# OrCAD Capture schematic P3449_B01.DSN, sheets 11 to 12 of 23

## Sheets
11 0012_3V3 DCDC and 1V8 LDO: size Custom
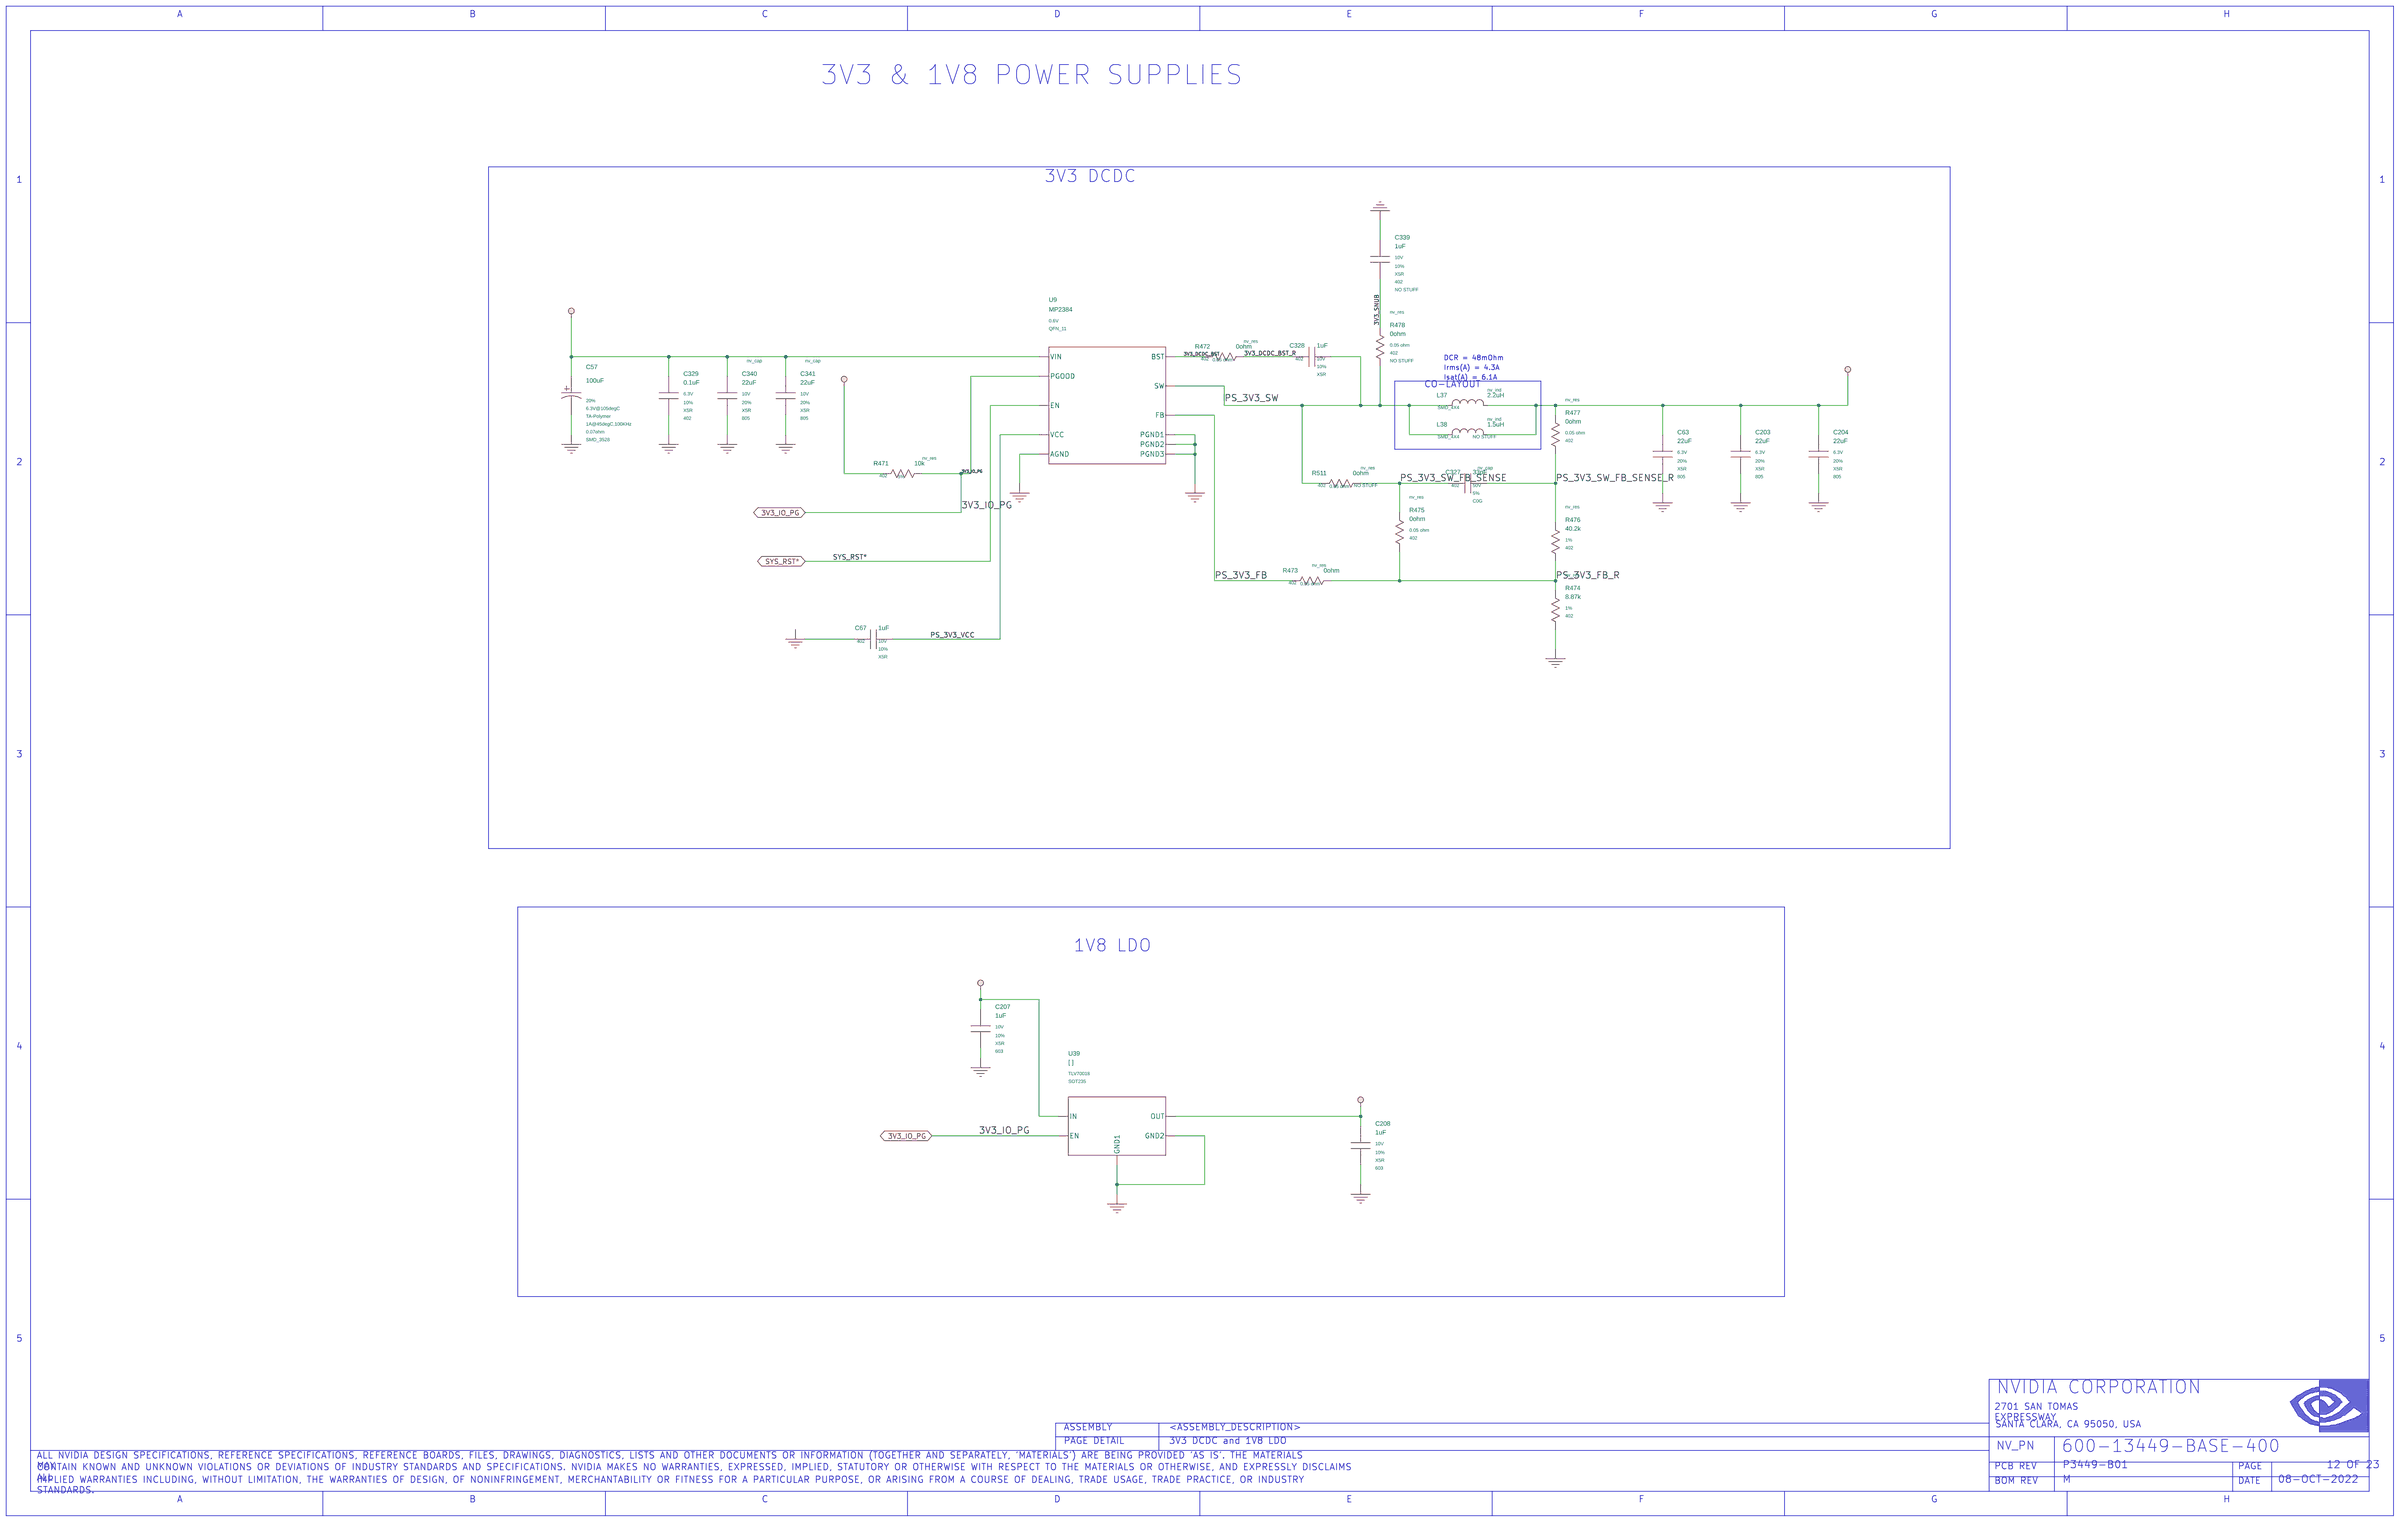
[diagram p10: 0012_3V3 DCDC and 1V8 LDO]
12 0011_DC Jack: size Custom
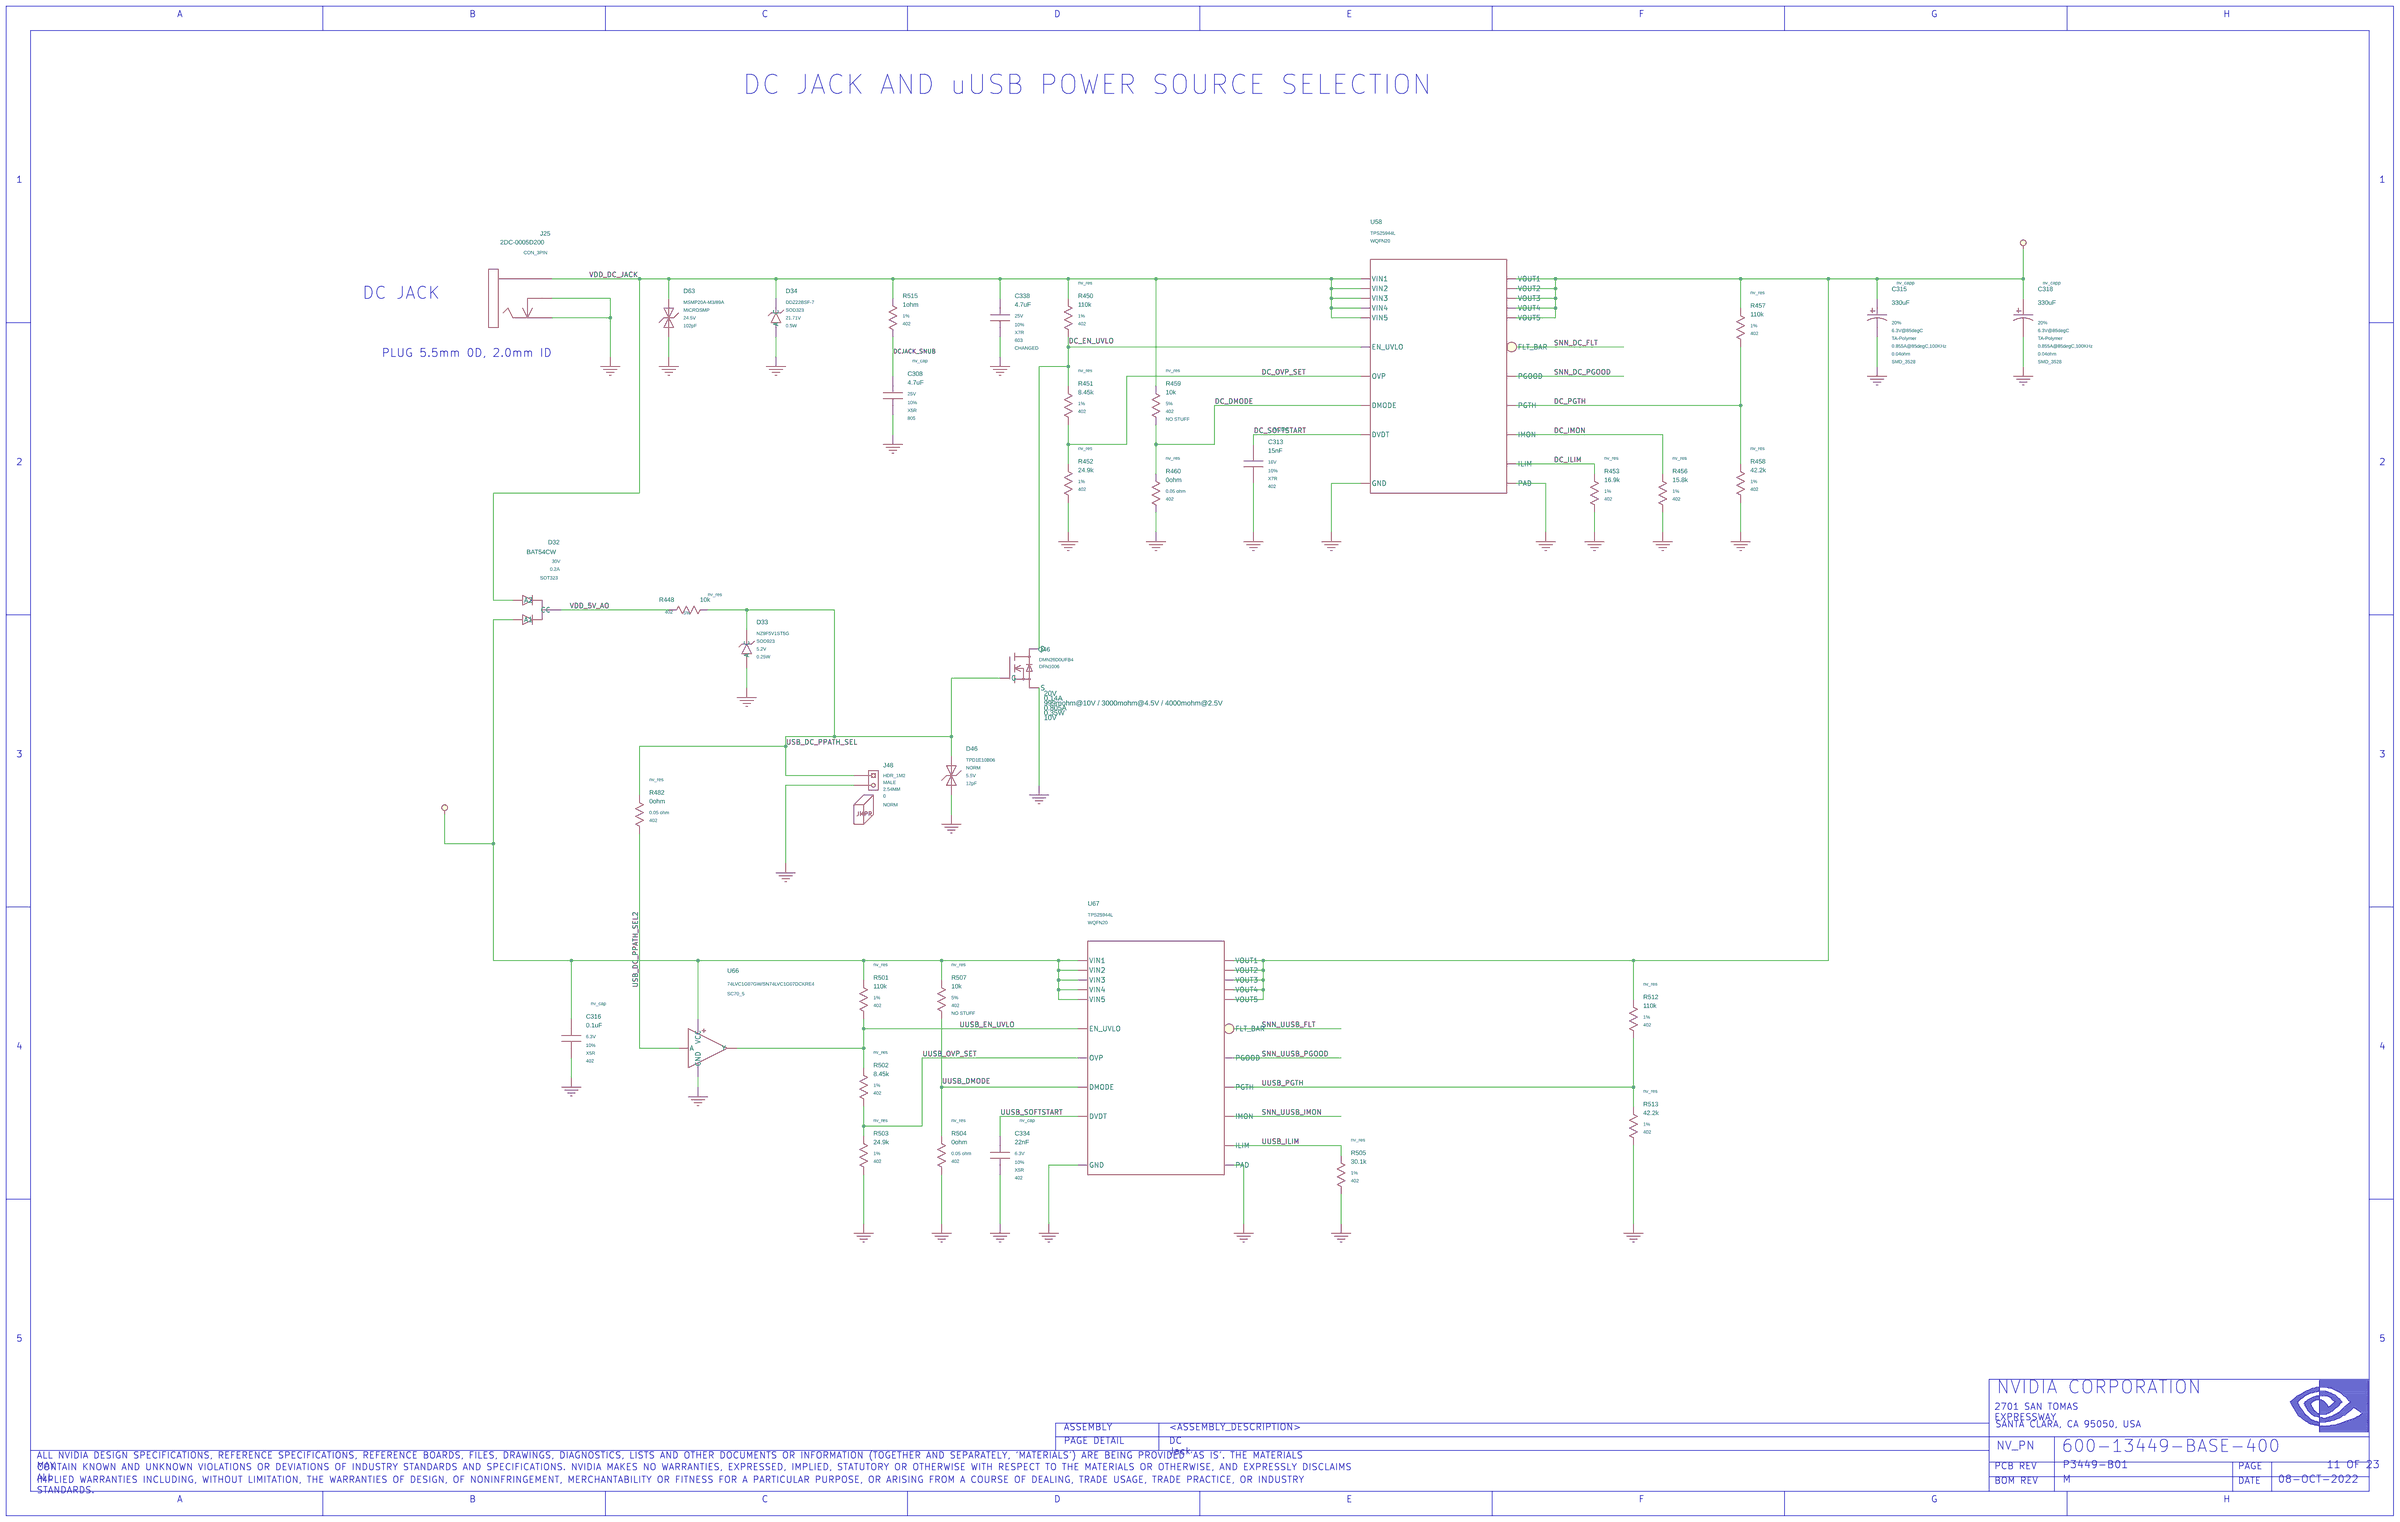
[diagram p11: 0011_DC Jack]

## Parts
sheet 0011_DC Jack
C308  4.7uF  [805]
C313  15nF  [402]
C315  330uF  [CAP_SMD_3528]
C316  0.1uF  [402]
C318  330uF  [CAP_SMD_3528]
C334  22nF  [402]
C338  4.7uF  [603]
D32  D_3PIN_CC  [SOT323]
D33  D_ZENER  [DIODE_SMD_SOD923]
D34  D_ZENER  [DIODE_SMD_SOD323_C]
D46  D_ESD  [DIODE_SMD_010X060]
D63  D_ESD  [DIODE_SMD_025X013]
J25  CON_PWR_JACK  [CON_PWR_003_TH_RA_145X090_C]
J48  HDR_1X2  [CON_HDR_001X002_TH_ST_M_P025]
Q46  Q_FET_N_ENH  [DFET_003_SMD_010X006_B]
R448  10k  [402]
R450  110k  [402]
R451  8.45k  [402]
R452  24.9k  [402]
R453  16.9k  [402]
R456  15.8k  [402]
R457  110k  [402]
R458  42.2k  [402]
R459  10k  [402]
R460  0ohm  [402]
R482  0ohm  [402]
R501  110k  [402]
R502  8.45k  [402]
R503  24.9k  [402]
R504  0ohm  [402]
R505  30.1k  [402]
R507  10k  [402]
R512  110k  [402]
R513  42.2k  [402]
R515  1ohm  [402]
U58  U_EFUSE  [QFN020R_P050_0040X0030_T026X016]
U66  U_BUF_OD  [SC70_5]
U67  U_EFUSE  [QFN020R_P050_0040X0030_T026X016]
sheet 0012_3V3 DCDC and 1V8 LDO
C57  100uF  [CAP_SMD_3528]
C63  22uF  [805]
C67  1uF  [402]
C203  22uF  [805]
C204  22uF  [805]
C207  1uF  [603]
C208  1uF  [603]
C327  33pF  [402]
C328  1uF  [402]
C329  0.1uF  [402]
C339  1uF  [402]
C340  22uF  [805]
C341  22uF  [805]
L37  2.2uH  [IND_NONRKO_SMD_040X040_H]
L38  1.5uH  [IND_NONRKO_SMD_040X040_J]
R471  10k  [402]
R472  0ohm  [402]
R473  0ohm  [402]
R474  8.87k  [402]
R475  0ohm  [402]
R476  40.2k  [402]
R477  0ohm  [402]
R478  0ohm  [402]
R511  0ohm  [402]
U9  0.6V  [QFN011Q_P050_0020]
U39  [ ]  [SOT23_5]

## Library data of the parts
C308 = C#1: ASSEMBLY: CONN_POWER; CDS_LIB: discrete; CDS_PART_NAME: C_0805-4.7UF,X5R,10%,25V,032-1141-000; CDS_PHYS_PART_NAME: C_0805-4.7UF,X5R,10%,25V,032-1141-000-032-1141-000,4.7UF; CDS_SEC: 1; CHIPS_PART_NAME: C; DEVICE_TYPENAME: C_0805-47UFX5R1025V032-1141-000-032-1141-00047UF; DRAWING: @P3449_B01_LIB.P3449_B01(SCH_1):PAGE11; IMPLEMENTATION_TYPE: X^@REFDES  %1    %2   @NV_PN; MAT: X5R; MAX_VOLTAGE: 25V; NV_PN: 032-1141-000; PATH: I350; PHYS_PAGE: 11; PSPICETEMPLATE: Pspice Model; ROT: 0; SEC: 1; SIGNAL_MODEL: nv_cap; TOL: 10%; VER: 1; XY: (-7800,5700)
C313 = C#1: ASSEMBLY: CONN_POWER; CDS_LIB: discrete; CDS_PART_NAME: C_0402-15NF,X7R,10%,16V,036-0119-000; CDS_PHYS_PART_NAME: C_0402-15NF,X7R,10%,16V,036-0119-000-036-0119-000,15NF; CDS_SEC: 1; CHIPS_PART_NAME: C; DEVICE_TYPENAME: C_0402-15NFX7R1016V036-0119-000-036-0119-00015NF; DRAWING: @P3449_B01_LIB.P3449_B01(SCH_1):PAGE11; MAT: X7R; MAX_VOLTAGE: 16V; NV_PN: 036-0119-000; PATH: I369; PHYS_PAGE: 11; ROT: 0; SEC: 1; SIGNAL_MODEL: nv_cap; TOL: 10%; VER: 1; XY: (-5950,5350)
C315 = C_POL: ASSEMBLY: CONN_POWER; CDS_LIB: discrete; CDS_PART_NAME: C_POL_SMD_3528-330UF,TA-POLYMER,20%,6.3V@85DEGC,0.04OHM,9.999UH,0.855A@85DEGC,100KHZ,032-0696-000; CDS_PHYS_PART_NAME: C_POL_SMD_3528-330UF,TA-POLYMER,20%,6.3V@85DEGC,0.04OHM,9.999UH,0.855A@85DEGC,100KHZ,032-0696-000-032-0696-000,330UF; CDS_SEC: 1; DEVICE_TYPENAME: C_POL_SMD_3528-330UFTA-POLYMER2063V85DEGC004OHM9999UH0855A85DEGC100KHZ032-0696-000-032-0696-000330UF; DRAWING: @P3449_B01_LIB.P3449_B01(SCH_1):PAGE11; ESL: 9.999uH; ESR: 0.04ohm; MAT: TA-Polymer; MAX_VOLTAGE: 6.3V@85degC; NV_PN: 032-0696-000; PACK_TYPE: SMD_3528; PATH: I385; PHYS_PAGE: 11; RIPPLE_CURRENT: 0.855A@85degC,100KHz; ROT: 0; SEC: 1; SIGNAL_MODEL: nv_capp; TOL: 20%; VER: 1; XY: (-2750,6100)
C316 = C#1: ASSEMBLY: CONN_POWER; CDS_LIB: discrete; CDS_PART_NAME: C_0402-0.1UF,X5R,10%,6.3V,039-0007-000; CDS_PHYS_PART_NAME: C_0402-0.1UF,X5R,10%,6.3V,039-0007-000-0.1UF,039-0007-000; CDS_SEC: 1; CHIPS_PART_NAME: C; DEVICE_TYPENAME: C_0402-01UFX5R1063V039-0007-000-01UF039-0007-000; DRAWING: @P3449_B01_LIB.P3449_B01(SCH_1):PAGE11; MAT: X5R; MAX_VOLTAGE: 6.3V; NV_PN: 039-0007-000; PATH: I398; PHYS_PAGE: 11; ROT: 0; SEC: 1; SIGNAL_MODEL: nv_cap; TOL: 10%; VER: 1; XY: (-9450,2400)
C318 = C_POL: ASSEMBLY: CONN_POWER; CDS_LIB: discrete; CDS_PART_NAME: C_POL_SMD_3528-330UF,TA-POLYMER,20%,6.3V@85DEGC,0.04OHM,9.999UH,0.855A@85DEGC,100KHZ,032-0696-000; CDS_PHYS_PART_NAME: C_POL_SMD_3528-330UF,TA-POLYMER,20%,6.3V@85DEGC,0.04OHM,9.999UH,0.855A@85DEGC,100KHZ,032-0696-000-032-0696-000,330UF; CDS_SEC: 1; DEVICE_TYPENAME: C_POL_SMD_3528-330UFTA-POLYMER2063V85DEGC004OHM9999UH0855A85DEGC100KHZ032-0696-000-032-0696-000330UF; DRAWING: @P3449_B01_LIB.P3449_B01(SCH_1):PAGE11; ESL: 9.999uH; ESR: 0.04ohm; MAT: TA-Polymer; MAX_VOLTAGE: 6.3V@85degC; NV_PN: 032-0696-000; PACK_TYPE: SMD_3528; PATH: I400; PHYS_PAGE: 11; RIPPLE_CURRENT: 0.855A@85degC,100KHz; ROT: 0; SEC: 1; SIGNAL_MODEL: nv_capp; TOL: 20%; VER: 1; XY: (-2000,6100)
C334 = C#1: ASSEMBLY: CONN_POWER; CDS_LIB: discrete; CDS_PART_NAME: C_0402-15NF,X7R,10%,16V,036-0119-000; CDS_PHYS_PART_NAME: C_0402-15NF,X7R,10%,16V,036-0119-000-036-0119-000,15NF; CDS_SEC: 1; CHIPS_PART_NAME: C; DEVICE_TYPENAME: C_0402-15NFX7R1016V036-0119-000-036-0119-00015NF; DRAWING: @P3449_B01_LIB.P3449_B01(SCH_1):PAGE11; MAT: X5R; MAX_VOLTAGE: 6.3V; NV_PN: 036-0119-000; PATH: I438; PHYS_PAGE: 11; ROT: 0; SEC: 1; SIGNAL_MODEL: nv_cap; TOL: 10%; VER: 1; XY: (-7250,1800)
C338 = C#1: ASSEMBLY: CONN_POWER; CDS_LIB: discrete; CDS_PART_NAME: C_0603-1UF,X5R,20%,25V,032-0882-000; CDS_PHYS_PART_NAME: C_0603-1UF,X5R,20%,25V,032-0882-000-032-0882-000,1UF; CDS_SEC: 1; CHIPS_PART_NAME: C; DEVICE_TYPENAME: C_0603-1UFX5R2025V032-0882-000-032-0882-0001UF; DRAWING: @P3449_B01_LIB.P3449_B01(SCH_1):PAGE11; MAT: X7R; MAX_VOLTAGE: 25V; NV_PN: 032-0882-000; PATH: I452; PHYS_PAGE: 11; ROT: 0; SEC: 1; SIGNAL_MODEL: nv_capp; SKU: CHANGED; TOL: 10%; VER: 1; XY: (-7250,6100)
D32 = D_3PIN_CC: ASSEMBLY: CONN_POWER; CDS_LIB: discrete; CDS_PART_NAME: D_3PIN_CC_SOT323-BAT54CW,1 PAIR - COMMON CATHODE,30V,0.6A,1V@0.1A,0.2A,091-0022-000; CDS_PHYS_PART_NAME: D_3PIN_CC_SOT323-BAT54CW,1 PAIR - COMMON CATHODE,30V,0.6A,1V@0.1A,0.2A,091-0022-000-091-0022-000; CDS_SEC: 1; CONFIGURATION: 1 Pair - Common Cathode; CONTINUOUS_CURRENT: 0.2A; DEVICE_TYPENAME: D_3PIN_CC_SOT323-BAT54CW1PAIR-COMMONCATHODE30V06A1V01A02A091-0022-000-091-0022-000; DRAWING: @P3449_B01_LIB.P3449_B01(SCH_1):PAGE11; FORWARD_VOLTAGE: 1V@0.1A; MAX_CURRENT: 0.6A; MAX_VOLTAGE: 30V; NV_NAME: BAT54CW; NV_PN: 091-0022-000; PATH: I373; PHYS_PAGE: 11; ROT: 2; SEC: 1; VER: 1; XY: (-9600,4600)
D33 = D_ZENER: ASSEMBLY: CONN_POWER; CDS_LIB: discrete; CDS_PART_NAME: D_ZENER_SOD923-NZ9F5V1ST5G,5.2V,5MA,0.9V@10MA,0.25W,090-0309-000; CDS_PHYS_PART_NAME: D_ZENER_SOD923-NZ9F5V1ST5G,5.2V,5MA,0.9V@10MA,0.25W,090-0309-000-090-0309-000; CDS_SEC: 1; CONTINUOUS_CURRENT: 0.25W; DEVICE_TYPENAME: D_ZENER_SOD923-NZ9F5V1ST5G52V5MA09V10MA025W090-0309-000-090-0309-000; DRAWING: @P3449_B01_LIB.P3449_B01(SCH_1):PAGE11; FORWARD_VOLTAGE: 0.9V@10mA; MAX_CURRENT: 5mA; MAX_VOLTAGE: 5.2V; NV_NAME: NZ9F5V1ST5G; NV_PN: 090-0309-000; PACK_TYPE: SOD923; PATH: I374; PHYS_PAGE: 11; ROT: 0; SEC: 1; VER: 2; XY: (-8550,4400)
D34 = D_ZENER: ASSEMBLY: CONN_POWER; CDS_LIB: discrete; CDS_PART_NAME: D_ZENER_SOD323-DDZ22BSF-7,21.71V,5MA,0.9V@10MA,0.5W,090-0377-000; CDS_PHYS_PART_NAME: D_ZENER_SOD323-DDZ22BSF-7,21.71V,5MA,0.9V@10MA,0.5W,090-0377-000-090-0377-000; CDS_SEC: 1; CONTINUOUS_CURRENT: 0.5W; DEVICE_TYPENAME: D_ZENER_SOD323-DDZ22BSF-72171V5MA09V10MA05W090-0377-000-090-0377-000; DRAWING: @P3449_B01_LIB.P3449_B01(SCH_1):PAGE11; FORWARD_VOLTAGE: 0.9V@10mA; MAX_CURRENT: 5mA; MAX_VOLTAGE: 21.71V; NV_NAME: DDZ22BSF-7; NV_PN: 090-0377-000; PACK_TYPE: SOD323; PATH: I404; PHYS_PAGE: 11; ROT: 0; SEC: 1; VER: 2; XY: (-8400,6100)
D46 = D_ESD: ASSEMBLY: CONN_POWER; BREAKDOWN_VOLTAGE_MIN_TYP: 6V; CAPACITANCE_MAX_TYP: 12pF; CDS_LIB: discrete; CDS_PART_NAME: D_ESD_NORM-TPD1E10B06,1 LINE,BI-DIRECTIONAL,5.5V,0.1UA,6V,10V@1A,12PF,090-0243-000; CDS_PHYS_PART_NAME: D_ESD_NORM-TPD1E10B06,1 LINE,BI-DIRECTIONAL,5.5V,0.1UA,6V,10V@1A,12PF,090-0243-000-090-0243-000; CDS_SEC: 1; CLAMPING_VOLTAGE: 10V@1A; CONFIGURATION: 1 Line; DEVICE_TYPENAME: D_ESD_NORM-TPD1E10B061LINEBI-DIRECTIONAL55V01UA6V10V1A12PF090-0243-000-090-0243-000; DRAWING: @P3449_B01_LIB.P3449_B01(SCH_1):PAGE11; MAX_REVERSE_LEAKAGE_CURRENT: 0.1uA; MAX_REVERSE_VOLTAGE: 5.5V; NV_NAME: TPD1E10B06; NV_PN: 090-0243-000; PACK_TYPE: NORM; PATH: I406; PHYS_PAGE: 11; POLARITY: Bi-Directional; ROT: 0; SEC: 1; VER: 2; XY: (-7500,3750)
D63 = D_ESD: ASSEMBLY: CONN_POWER; BREAKDOWN_VOLTAGE_MIN_TYP: 22.2V; CAPACITANCE_MAX_TYP: 102pF; CDS_LIB: discrete; CDS_PART_NAME: D_ESD_MICROSMP-MSMP20A-M3/89A,1 LINE,UNI-DIRECTIONAL,24.5V,1UA,22.2V,42.8V@23.4A,102PF,090-0378-000; CDS_PHYS_PART_NAME: D_ESD_MICROSMP-MSMP20A-M3/89A,1 LINE,UNI-DIRECTIONAL,24.5V,1UA,22.2V,42.8V@23.4A,102PF,090-0378-000-090-0378-000; CDS_SEC: 1; CLAMPING_VOLTAGE: 42.8V@23.4A; CONFIGURATION: 1 Line; DEVICE_TYPENAME: D_ESD_MICROSMP-MSMP20A-M389A1LINEUNI-DIRECTIONAL245V1UA222V428V234A102PF090-0378-000-090-0378-000; DRAWING: @P3449_B01_LIB.P3449_B01(SCH_1):PAGE11; MAX_REVERSE_LEAKAGE_CURRENT: 1uA; MAX_REVERSE_VOLTAGE: 24.5V; NV_NAME: MSMP20A-M3/89A; NV_PN: 090-0378-000; PACK_TYPE: MICROSMP; PATH: I432; PHYS_PAGE: 11; POLARITY: Uni-Directional; ROT: 0; SEC: 1; VER: 2; XY: (-8950,6100)
J25 = CON_PWR_JACK: ANGLE: 90; ASSEMBLY: CONN_POWER; CDS_LIB: electro_mechanic; CDS_PART_NAME: CON_PWR_JACK_CON_3PIN-2DC-0005D200,FEMALE,N/A,90,YES,NO,NO,NO,NO,24V,5A,064-0377-000; CDS_PHYS_PART_NAME: CON_PWR_JACK_CON_3PIN-2DC-0005D200,FEMALE,N/A,90,YES,NO,NO,NO,NO,24V,5A,064-0377-000-064-0377-000; CDS_SEC: 1; DEVICE_TYPENAME: CON_PWR_JACK_CON_3PIN-2DC-0005D200FEMALENA90YESNONONONO24V5A064-0377-000-064-0377-000; DRAWING: @P3449_B01_LIB.P3449_B01(SCH_1):PAGE11; EMI_GROUND_TAB: NO; GENDER: FEMALE; LATCHING: NO; MAX_CURRENT: 5A; MAX_VOLTAGE: 24V; NV_NAME: 2DC-0005D200; NV_PN: 064-0377-000; PACK_TYPE: CON_3PIN; PATH: I220; PHYS_PAGE: 11; PITCH: N/A; REFLOW: YES; ROT: 2; SEC: 1; SHIELDED: NO; SHROUDED: NO; VER: 1; XY: (-9850,6300)
J48 = HDR_1X2: ANGLE: 0; ASSEMBLY: CONN_POWER; CDS_LIB: electro_mechanic; CDS_PART_NAME: HDR_1X2_NORM-HDR_1M2,MALE,2.54MM,0,NO,NO,NO,250V,3A,074-0117-000; CDS_PHYS_PART_NAME: HDR_1X2_NORM-HDR_1M2,MALE,2.54MM,0,NO,NO,NO,250V,3A,074-0117-000-074-0117-000; CDS_SEC: 1; DEVICE_TYPENAME: HDR_1X2_NORM-HDR_1M2MALE254MM0NONONO250V3A074-0117-000-074-0117-000; DRAWING: @P3449_B01_LIB.P3449_B01(SCH_1):PAGE11; GENDER: MALE; LATCHING: NO; MAX_CURRENT: 3A; MAX_VOLTAGE: 250V; NV_NAME: HDR_1M2; NV_PN: 074-0117-000; PACK_TYPE: NORM; PATH: I361; PHYS_PAGE: 11; PITCH: 2.54MM; REFLOW: NO; ROT: 0; SEC: 1; SEC_TYPE: NORM; SHROUDED: NO; VER: 3; XY: (-7900,3750)
Q46 = Q_FET_N_ENH#1: ASSEMBLY: CONN_POWER; CDS_LIB: discrete; CDS_PART_NAME: Q_FET_N_ENH_DFN1006-DMN26D0UFB4,20V,999MOHM@10V / 3000MOHM@4.5V / 4000MOHM@2.5V,0.14A,0.805A,10V,0.35W,999NC@10V / 0NC@4.5V / A; CDS_PHYS_PART_NAME: Q_FET_N_ENH_DFN1006-DMN26D0UFB4,20V,999MOHM@10V / 3000MOHM@4.5V / 4000MOHM@2.5V,0.14A,0.805A,10V,0.35W,999NC@10V / 0NC@4.5V / B; CDS_SEC: 1; CONTINUOUS_CURRENT: 0.14A; CaptureCellPackProp: Q_FET_N_ENH##1; DEVICE_TYPENAME: Q_FET_N_ENH_DFN1006-DMN26D0UFB420V999MOHM10V3000MOHM45V4000MOHM25V014A0805A10V035W999NC10V0NC45VB; DRAWING: @P3449_B01_LIB.P3449_B01(SCH_1):PAGE11; MAX_CURRENT: 0.805A; MAX_VOLTAGE: 20V; MAX_WATTAGE: 0.35W; NV_NAME: DMN26D0UFB4; NV_PN: 300-0868-000; PACK_TYPE: DFN1006; PATH: I377; PHYS_PAGE: 11; Q_G: 999nC@10V / 0nC@4.5V / 999nC@2.5V; ROT: 0; R_DS_ON: 999mohm@10V / 3000mohm@4.5V / 4000mohm@2.5V; SEC: 1; VER: 2; V_BE_GS: 10V; XY: (-7150,4300)
R448 = R#1: ASSEMBLY: CONN_POWER; CDS_LIB: discrete; CDS_PART_NAME: R_0402-10K,5 %,62.5MW,195-0486-000; CDS_PHYS_PART_NAME: R_0402-10K,5 %,62.5MW,195-0486-000-10K,195-0486-000; CDS_SEC: 1; CHIPS_PART_NAME: R; DEVICE_TYPENAME: R_0402-10K5625MW195-0486-000-10K195-0486-000; DRAWING: @P3449_B01_LIB.P3449_B01(SCH_1):PAGE11; MAX_WATTAGE: 62.5mW; NV_PN: 195-0486-000; PATH: I380; PHYS_PAGE: 11; ROT: 0; SEC: 1; SIGNAL_MODEL: nv_res; TOL: 5%; VER: 1; XY: (-8850,4600)
R450 = R: ASSEMBLY: CONN_POWER; CDS_LIB: discrete; CDS_PART_NAME: R_0402-110K,1 %,62.5MW,195-0026-000; CDS_PHYS_PART_NAME: R_0402-110K,1 %,62.5MW,195-0026-000-110K,195-0026-000; CDS_SEC: 1; DEVICE_TYPENAME: R_0402-110K1625MW195-0026-000-110K195-0026-000; DRAWING: @P3449_B01_LIB.P3449_B01(SCH_1):PAGE11; MAX_WATTAGE: 62.5mW; NV_PN: 195-0026-000; PATH: I367; PHYS_PAGE: 11; ROT: 0; SEC: 1; SIGNAL_MODEL: nv_res; TOL: 1%; VER: 2; XY: (-6900,6100)
R451 = R: ASSEMBLY: CONN_POWER; CDS_LIB: discrete; CDS_PART_NAME: R_0402-8.45K,1 %,62.5MW,195-0449-000; CDS_PHYS_PART_NAME: R_0402-8.45K,1 %,62.5MW,195-0449-000-195-0449-000,8.45K; CDS_SEC: 1; DEVICE_TYPENAME: R_0402-845K1625MW195-0449-000-195-0449-000845K; DRAWING: @P3449_B01_LIB.P3449_B01(SCH_1):PAGE11; MAX_WATTAGE: 62.5mW; NV_PN: 195-0449-000; PATH: I383; PHYS_PAGE: 11; ROT: 0; SEC: 1; SIGNAL_MODEL: nv_res; TOL: 1%; VER: 2; XY: (-6900,5650)
R452 = R: ASSEMBLY: CONN_POWER; CDS_LIB: discrete; CDS_PART_NAME: R_0402-24.9K,1 %,62.5MW,195-0195-000; CDS_PHYS_PART_NAME: R_0402-24.9K,1 %,62.5MW,195-0195-000-195-0195-000,24.9K; CDS_SEC: 1; DEVICE_TYPENAME: R_0402-249K1625MW195-0195-000-195-0195-000249K; DRAWING: @P3449_B01_LIB.P3449_B01(SCH_1):PAGE11; MAX_WATTAGE: 62.5mW; NV_PN: 195-0195-000; PATH: I384; PHYS_PAGE: 11; ROT: 0; SEC: 1; SIGNAL_MODEL: nv_res; TOL: 1%; VER: 2; XY: (-6900,5250)
R453 = R: ASSEMBLY: CONN_POWER; CDS_LIB: discrete; CDS_PART_NAME: R_0402-16.9K,1 %,62.5MW,195-0115-000; CDS_PHYS_PART_NAME: R_0402-16.9K,1 %,62.5MW,195-0115-000-16.9K,195-0115-000; CDS_SEC: 1; DEVICE_TYPENAME: R_0402-169K1625MW195-0115-000-169K195-0115-000; DRAWING: @P3449_B01_LIB.P3449_B01(SCH_1):PAGE11; MAX_WATTAGE: 62.5mW; NV_PN: 195-0115-000; PATH: I371; PHYS_PAGE: 11; ROT: 0; SEC: 1; SIGNAL_MODEL: nv_res; TOL: 1%; VER: 2; XY: (-4200,5200)
R456 = R: ASSEMBLY: CONN_POWER; CDS_LIB: discrete; CDS_PART_NAME: R_0402-15.8K,1 %,62.5MW,195-0100-000; CDS_PHYS_PART_NAME: R_0402-15.8K,1 %,62.5MW,195-0100-000-15.8K,195-0100-000; CDS_SEC: 1; DEVICE_TYPENAME: R_0402-158K1625MW195-0100-000-158K195-0100-000; DRAWING: @P3449_B01_LIB.P3449_B01(SCH_1):PAGE11; MAX_WATTAGE: 62.5mW; NV_PN: 195-0100-000; PATH: I390; PHYS_PAGE: 11; ROT: 0; SEC: 1; SIGNAL_MODEL: nv_res; TOL: 1%; VER: 2; XY: (-3850,5200)
R457 = R: ASSEMBLY: CONN_POWER; CDS_LIB: discrete; CDS_PART_NAME: R_0402-110K,1 %,62.5MW,195-0026-000; CDS_PHYS_PART_NAME: R_0402-110K,1 %,62.5MW,195-0026-000-110K,195-0026-000; CDS_SEC: 1; DEVICE_TYPENAME: R_0402-110K1625MW195-0026-000-110K195-0026-000; DRAWING: @P3449_B01_LIB.P3449_B01(SCH_1):PAGE11; MAX_WATTAGE: 62.5mW; NV_PN: 195-0026-000; PATH: I392; PHYS_PAGE: 11; ROT: 0; SEC: 1; SIGNAL_MODEL: nv_res; TOL: 1%; VER: 2; XY: (-3450,6050)
R458 = R: ASSEMBLY: CONN_POWER; CDS_LIB: discrete; CDS_PART_NAME: R_0402-42.2K,1 %,62.5MW,195-0305-000; CDS_PHYS_PART_NAME: R_0402-42.2K,1 %,62.5MW,195-0305-000-195-0305-000,42.2K; CDS_SEC: 1; DEVICE_TYPENAME: R_0402-422K1625MW195-0305-000-195-0305-000422K; DRAWING: @P3449_B01_LIB.P3449_B01(SCH_1):PAGE11; MAX_WATTAGE: 62.5mW; NV_PN: 195-0305-000; PATH: I391; PHYS_PAGE: 11; ROT: 0; SEC: 1; SIGNAL_MODEL: nv_res; TOL: 1%; VER: 2; XY: (-3450,5250)
R459 = R: ASSEMBLY: CONN_POWER; CDS_LIB: discrete; CDS_PART_NAME: R_0402-10K,5 %,62.5MW,195-0486-000; CDS_PHYS_PART_NAME: R_0402-10K,5 %,62.5MW,195-0486-000-10K,195-0486-000; CDS_SEC: 1; DEVICE_TYPENAME: R_0402-10K5625MW195-0486-000-10K195-0486-000; DRAWING: @P3449_B01_LIB.P3449_B01(SCH_1):PAGE11; MAX_WATTAGE: 62.5mW; NV_PN: 195-0486-000; PATH: I395; PHYS_PAGE: 11; ROT: 0; SEC: 1; SIGNAL_MODEL: nv_res; SKU: NO STUFF; TOL: 5%; VER: 2; XY: (-6450,5650)
R460 = R: ASSEMBLY: CONN_POWER; CDS_LIB: discrete; CDS_PART_NAME: R_0402-0OHM,0.05 OHM,62.5MW,195-2655-000; CDS_PHYS_PART_NAME: R_0402-0OHM,0.05 OHM,62.5MW,195-2655-000-0OHM,195-2655-000; CDS_SEC: 1; DEVICE_TYPENAME: R_0402-0OHM005OHM625MW195-2655-000-0OHM195-2655-000; DRAWING: @P3449_B01_LIB.P3449_B01(SCH_1):PAGE11; MAX_WATTAGE: 62.5mW; NV_PN: 195-2655-000; PATH: I396; PHYS_PAGE: 11; ROT: 0; SEC: 1; SIGNAL_MODEL: nv_res; TOL: 0.05 ohm; VER: 2; XY: (-6450,5200)
R482 = R: ASSEMBLY: CONN_POWER; CDS_LIB: discrete; CDS_PART_NAME: R_0402-0OHM,0.05 OHM,62.5MW,195-2655-000; CDS_PHYS_PART_NAME: R_0402-0OHM,0.05 OHM,62.5MW,195-2655-000-0OHM,195-2655-000; CDS_SEC: 1; DEVICE_TYPENAME: R_0402-0OHM005OHM625MW195-2655-000-0OHM195-2655-000; DRAWING: @P3449_B01_LIB.P3449_B01(SCH_1):PAGE11; MAX_WATTAGE: 62.5mW; NV_PN: 195-2655-000; PATH: I416; PHYS_PAGE: 11; ROT: 0; SEC: 1; SIGNAL_MODEL: nv_res; TOL: 0.05 ohm; VER: 2; XY: (-9100,3550)
R501 = R: ASSEMBLY: CONN_POWER; CDS_LIB: discrete; CDS_PART_NAME: R_0402-110K,1 %,62.5MW,195-0026-000; CDS_PHYS_PART_NAME: R_0402-110K,1 %,62.5MW,195-0026-000-110K,195-0026-000; CDS_SEC: 1; DEVICE_TYPENAME: R_0402-110K1625MW195-0026-000-110K195-0026-000; DRAWING: @P3449_B01_LIB.P3449_B01(SCH_1):PAGE11; MAX_WATTAGE: 62.5mW; NV_PN: 195-0026-000; PATH: I443; PHYS_PAGE: 11; ROT: 0; SEC: 1; SIGNAL_MODEL: nv_res; TOL: 1%; VER: 2; XY: (-7950,2600)
R502 = R: ASSEMBLY: CONN_POWER; CDS_LIB: discrete; CDS_PART_NAME: R_0402-8.45K,1 %,62.5MW,195-0449-000; CDS_PHYS_PART_NAME: R_0402-8.45K,1 %,62.5MW,195-0449-000-195-0449-000,8.45K; CDS_SEC: 1; DEVICE_TYPENAME: R_0402-845K1625MW195-0449-000-195-0449-000845K; DRAWING: @P3449_B01_LIB.P3449_B01(SCH_1):PAGE11; MAX_WATTAGE: 62.5mW; NV_PN: 195-0449-000; PATH: I444; PHYS_PAGE: 11; ROT: 0; SEC: 1; SIGNAL_MODEL: nv_res; TOL: 1%; VER: 2; XY: (-7950,2150)
R503 = R: ASSEMBLY: CONN_POWER; CDS_LIB: discrete; CDS_PART_NAME: R_0402-24.9K,1 %,62.5MW,195-0195-000; CDS_PHYS_PART_NAME: R_0402-24.9K,1 %,62.5MW,195-0195-000-195-0195-000,24.9K; CDS_SEC: 1; DEVICE_TYPENAME: R_0402-249K1625MW195-0195-000-195-0195-000249K; DRAWING: @P3449_B01_LIB.P3449_B01(SCH_1):PAGE11; MAX_WATTAGE: 62.5mW; NV_PN: 195-0195-000; PATH: I445; PHYS_PAGE: 11; ROT: 0; SEC: 1; SIGNAL_MODEL: nv_res; TOL: 1%; VER: 2; XY: (-7950,1800)
R504 = R: ASSEMBLY: CONN_POWER; CDS_LIB: discrete; CDS_PART_NAME: R_0402-0OHM,0.05 OHM,62.5MW,195-2655-000; CDS_PHYS_PART_NAME: R_0402-0OHM,0.05 OHM,62.5MW,195-2655-000-0OHM,195-2655-000; CDS_SEC: 1; DEVICE_TYPENAME: R_0402-0OHM005OHM625MW195-2655-000-0OHM195-2655-000; DRAWING: @P3449_B01_LIB.P3449_B01(SCH_1):PAGE11; MAX_WATTAGE: 62.5mW; NV_PN: 195-2655-000; PATH: I441; PHYS_PAGE: 11; ROT: 0; SEC: 1; SIGNAL_MODEL: nv_res; TOL: 0.05 ohm; VER: 2; XY: (-7550,1800)
R505 = R: ASSEMBLY: CONN_POWER; CDS_LIB: discrete; CDS_PART_NAME: R_0402-30.1K,1 %,62.5MW,195-0270-000; CDS_PHYS_PART_NAME: R_0402-30.1K,1 %,62.5MW,195-0270-000-195-0270-000,35.7K; CDS_SEC: 1; DEVICE_TYPENAME: R_0402-357K1625MW195-0270-000-195-0270-000357K; DRAWING: @P3449_B01_LIB.P3449_B01(SCH_1):PAGE11; MAX_WATTAGE: 62.5mW; NV_PN: 195-0270-000; PATH: I434; PHYS_PAGE: 11; ROT: 0; SEC: 1; SIGNAL_MODEL: nv_res; TOL: 1%; VER: 2; XY: (-5500,1700)
R507 = R: ASSEMBLY: CONN_POWER; CDS_LIB: discrete; CDS_PART_NAME: R_0402-10K,5 %,62.5MW,195-0486-000; CDS_PHYS_PART_NAME: R_0402-10K,5 %,62.5MW,195-0486-000-10K,195-0486-000; CDS_SEC: 1; DEVICE_TYPENAME: R_0402-10K5625MW195-0486-000-10K195-0486-000; DRAWING: @P3449_B01_LIB.P3449_B01(SCH_1):PAGE11; MAX_WATTAGE: 62.5mW; NV_PN: 195-0486-000; PATH: I451; PHYS_PAGE: 11; ROT: 0; SEC: 1; SIGNAL_MODEL: nv_res; SKU: NO STUFF; TOL: 5%; VER: 2; XY: (-7550,2600)
R512 = R: ASSEMBLY: CONN_POWER; CDS_LIB: discrete; CDS_PART_NAME: R_0402-110K,1 %,62.5MW,195-0026-000; CDS_PHYS_PART_NAME: R_0402-110K,1 %,62.5MW,195-0026-000-110K,195-0026-000; CDS_SEC: 1; DEVICE_TYPENAME: R_0402-110K1625MW195-0026-000-110K195-0026-000; DRAWING: @P3449_B01_LIB.P3449_B01(SCH_1):PAGE11; MAX_WATTAGE: 62.5mW; NV_PN: 195-0026-000; PATH: I454; PHYS_PAGE: 11; ROT: 0; SEC: 1; SIGNAL_MODEL: nv_res; TOL: 1%; VER: 2; XY: (-4000,2500)
R513 = R: ASSEMBLY: CONN_POWER; CDS_LIB: discrete; CDS_PART_NAME: R_0402-42.2K,1 %,62.5MW,195-0305-000; CDS_PHYS_PART_NAME: R_0402-42.2K,1 %,62.5MW,195-0305-000-195-0305-000,42.2K; CDS_SEC: 1; DEVICE_TYPENAME: R_0402-422K1625MW195-0305-000-195-0305-000422K; DRAWING: @P3449_B01_LIB.P3449_B01(SCH_1):PAGE11; MAX_WATTAGE: 62.5mW; NV_PN: 195-0305-000; PATH: I455; PHYS_PAGE: 11; ROT: 0; SEC: 1; SIGNAL_MODEL: nv_res; TOL: 1%; VER: 2; XY: (-4000,1950)
R515 = R: ASSEMBLY: CONN_POWER; CDS_LIB: discrete; CDS_PART_NAME: R_0402-5.6OHM,5 %,62.5MW,195-0609-000; CDS_PHYS_PART_NAME: R_0402-5.6OHM,5 %,62.5MW,195-0609-000-195-0609-000,5.6OHM; CDS_SEC: 1; DEVICE_TYPENAME: R_0402-56OHM5625MW195-0609-000-195-0609-00056OHM; DRAWING: @P3449_B01_LIB.P3449_B01(SCH_1):PAGE11; MAX_WATTAGE: 62.5mW; NV_PN: 195-0609-000; PATH: I457; PHYS_PAGE: 11; ROT: 0; SEC: 1; TOL: 1%; VER: 2; XY: (-7800,6100)
U58 = U_EFUSE#1: ASSEMBLY: CONN_POWER; CDS_LIB: power_supply; CDS_PART_NAME: U_EFUSE_WQFN20-TPS25944L,-0.3V..18V,2.7V..20V,5.2A,OTHER,315-1109-000; CDS_PHYS_PART_NAME: U_EFUSE_WQFN20-TPS25944L,-0.3V..18V,2.7V..20V,5.2A,OTHER,315-1109-000-315-1109-000; CDS_SEC: 1; DEVICE_TYPENAME: U_EFUSE_WQFN20-TPS25944L-03V18V27V20V52AOTHER315-1109-000-315-1109-000; DRAWING: @P3449_B01_LIB.P3449_B01(SCH_1):PAGE11; MAX_CURRENT: 5.2A; MAX_VOLTAGE: 2.7V..20V; NV_NAME: TPS25944L; NV_PN: 315-1109-000; OUTPUT_VOLTAGE: -0.3V..18V; PACK_TYPE: WQFN20; PATH: I386; PHYS_PAGE: 11; ROT: 0; SEC: 1; TYPE: Other; VER: 3; XY: (-5000,5800)
U66 = U_BUF_OD: ASSEMBLY: CONN_POWER; CDS_LIB: logic; CDS_PART_NAME: U_BUF_OD_SC70_5-74LVC1G07GW/SN74LVC1G07DCKRE4,BUFFER - OPEN DRAIN,115-0138-000; CDS_PHYS_PART_NAME: U_BUF_OD_SC70_5-74LVC1G07GW/SN74LVC1G07DCKRE4,BUFFER - OPEN DRAIN,115-0138-000-115-0138-000; CDS_SEC: 1; DEVICE_TYPENAME: U_BUF_OD_SC70_5-74LVC1G07GWSN74LVC1G07DCKRE4BUFFER-OPENDRAIN115-0138-000-115-0138-000; DRAWING: @P3449_B01_LIB.P3449_B01(SCH_1):PAGE11; FUNCTION: Buffer - Open Drain; NV_NAME: 74LVC1G07GW/SN74LVC1G07DCKRE4; NV_PN: 115-0138-000; PATH: I450; PHYS_PAGE: 11; ROT: 0; SEC: 1; VER: 1; XY: (-8750,2350)
U67 = U_EFUSE#1: ASSEMBLY: CONN_POWER; CDS_LIB: power_supply; CDS_PART_NAME: U_EFUSE_WQFN20-TPS25944L,-0.3V..18V,2.7V..20V,5.2A,OTHER,315-1109-000; CDS_PHYS_PART_NAME: U_EFUSE_WQFN20-TPS25944L,-0.3V..18V,2.7V..20V,5.2A,OTHER,315-1109-000-315-1109-000; CDS_SEC: 1; DEVICE_TYPENAME: U_EFUSE_WQFN20-TPS25944L-03V18V27V20V52AOTHER315-1109-000-315-1109-000; DRAWING: @P3449_B01_LIB.P3449_B01(SCH_1):PAGE11; MAX_CURRENT: 5.2A; MAX_VOLTAGE: 2.7V..20V; NV_NAME: TPS25944L; NV_PN: 315-1109-000; OUTPUT_VOLTAGE: -0.3V..18V; PACK_TYPE: WQFN20; PATH: I433; PHYS_PAGE: 11; ROT: 0; SEC: 1; TYPE: Other; VER: 3; XY: (-6450,2300)
C57 = C_POL: ASSEMBLY: 3V3_DCDC; CDS_LIB: discrete; CDS_PART_NAME: C_POL_SMD_3528-100UF,TA-POLYMER,20%,6.3V@105DEGC,0.07OHM,9.999UH,1A@45DEGC,100KHZ,041-0092-000; CDS_PHYS_PART_NAME: C_POL_SMD_3528-100UF,TA-POLYMER,20%,6.3V@105DEGC,0.07OHM,9.999UH,1A@45DEGC,100KHZ,041-0092-000-041-0092-000,100UF; CDS_SEC: 1; DEVICE_TYPENAME: C_POL_SMD_3528-100UFTA-POLYMER2063V105DEGC007OHM9999UH1A45DEGC100KHZ041-0092-000-041-0092-000100UF; DRAWING: @P3449_B01_LIB.P3449_B01(SCH_1):PAGE12; ESL: 9.999uH; ESR: 0.07ohm; MAT: TA-Polymer; MAX_VOLTAGE: 6.3V@105degC; NV_PN: 041-0092-000; PACK_TYPE: SMD_3528; PATH: I27; PHYS_PAGE: 12; RIPPLE_CURRENT: 1A@45degC,100KHz; ROT: 0; SEC: 1; SIGNAL_MODEL: nv_capp; TOL: 20%; VER: 1; XY: (-9250,5600)
C63 = C#1: ASSEMBLY: 3V3_DCDC; CDS_LIB: discrete; CDS_PART_NAME: C_0805-22UF,X5R,20%,6.3V,039-0127-000; CDS_PHYS_PART_NAME: C_0805-22UF,X5R,20%,6.3V,039-0127-000-039-0127-000,22UF; CDS_SEC: 1; CHIPS_PART_NAME: C; DEVICE_TYPENAME: C_0805-22UFX5R2063V039-0127-000-039-0127-00022UF; DRAWING: @P3449_B01_LIB.P3449_B01(SCH_1):PAGE12; MAT: X5R; MAX_VOLTAGE: 6.3V; NV_PN: 039-0127-000; PATH: I19; PHYS_PAGE: 12; ROT: 0; SEC: 1; SIGNAL_MODEL: nv_capp; TOL: 20%; VER: 1; XY: (-3650,5300)
C67 = C: ASSEMBLY: 3V3_DCDC; CDS_LIB: discrete; CDS_PART_NAME: C_0402-1UF,X5R,10%,10V,039-0140-000; CDS_PHYS_PART_NAME: C_0402-1UF,X5R,10%,10V,039-0140-000-039-0140-000,1UF; CDS_SEC: 1; DEVICE_TYPENAME: C_0402-1UFX5R1010V039-0140-000-039-0140-0001UF; DRAWING: @P3449_B01_LIB.P3449_B01(SCH_1):PAGE12; MAT: X5R; MAX_VOLTAGE: 10V; NV_PN: 039-0140-000; PATH: I77; PHYS_PAGE: 12; ROT: 0; SEC: 1; SIGNAL_MODEL: nv_cap; TOL: 10%; VER: 2; XY: (-7700,4350)
C203 = C#1: ASSEMBLY: 3V3_DCDC; CDS_LIB: discrete; CDS_PART_NAME: C_0805-22UF,X5R,20%,6.3V,039-0127-000; CDS_PHYS_PART_NAME: C_0805-22UF,X5R,20%,6.3V,039-0127-000-039-0127-000,22UF; CDS_SEC: 1; CHIPS_PART_NAME: C; DEVICE_TYPENAME: C_0805-22UFX5R2063V039-0127-000-039-0127-00022UF; DRAWING: @P3449_B01_LIB.P3449_B01(SCH_1):PAGE12; MAT: X5R; MAX_VOLTAGE: 6.3V; NV_PN: 039-0127-000; PATH: I17; PHYS_PAGE: 12; ROT: 0; SEC: 1; SIGNAL_MODEL: nv_capp; TOL: 20%; VER: 1; XY: (-3250,5300)
C204 = C#1: ASSEMBLY: 3V3_DCDC; CDS_LIB: discrete; CDS_PART_NAME: C_0805-22UF,X5R,20%,6.3V,039-0127-000; CDS_PHYS_PART_NAME: C_0805-22UF,X5R,20%,6.3V,039-0127-000-039-0127-000,22UF; CDS_SEC: 1; CHIPS_PART_NAME: C; DEVICE_TYPENAME: C_0805-22UFX5R2063V039-0127-000-039-0127-00022UF; DRAWING: @P3449_B01_LIB.P3449_B01(SCH_1):PAGE12; MAT: X5R; MAX_VOLTAGE: 6.3V; NV_PN: 039-0127-000; PATH: I15; PHYS_PAGE: 12; ROT: 0; SEC: 1; SIGNAL_MODEL: nv_capp; TOL: 20%; VER: 1; XY: (-2850,5300)
C207 = C#1: ASSEMBLY: 1V8_LDO; CDS_LIB: discrete; CDS_PART_NAME: C_0603-1UF,X5R,10%,10V,039-0038-000; CDS_PHYS_PART_NAME: C_0603-1UF,X5R,10%,10V,039-0038-000-039-0038-000,1UF; CDS_SEC: 1; CHIPS_PART_NAME: C; DEVICE_TYPENAME: C_0603-1UFX5R1010V039-0038-000-039-0038-0001UF; DRAWING: @P3449_B01_LIB.P3449_B01(SCH_1):PAGE12; MAT: X5R; MAX_VOLTAGE: 10V; NV_PN: 039-0038-000; PATH: I47; PHYS_PAGE: 12; ROT: 0; SEC: 1; SIGNAL_MODEL: nv_cap; TOL: 10%; VER: 1; XY: (-7150,2350)
C208 = C#1: ASSEMBLY: 1V8_LDO; CDS_LIB: discrete; CDS_PART_NAME: C_0603-1UF,X5R,10%,10V,039-0038-000; CDS_PHYS_PART_NAME: C_0603-1UF,X5R,10%,10V,039-0038-000-039-0038-000,1UF; CDS_SEC: 1; CHIPS_PART_NAME: C; DEVICE_TYPENAME: C_0603-1UFX5R1010V039-0038-000-039-0038-0001UF; DRAWING: @P3449_B01_LIB.P3449_B01(SCH_1):PAGE12; MAT: X5R; MAX_VOLTAGE: 10V; NV_PN: 039-0038-000; PATH: I44; PHYS_PAGE: 12; ROT: 0; SEC: 1; SIGNAL_MODEL: nv_cap; TOL: 10%; VER: 1; XY: (-5200,1750)
C327 = C: ASSEMBLY: 3V3_DCDC; CDS_LIB: discrete; CDS_PART_NAME: C_0402-33PF,C0G,5%,50V,035-0028-000; CDS_PHYS_PART_NAME: C_0402-33PF,C0G,5%,50V,035-0028-000-035-0028-000,33PF; CDS_SEC: 1; DEVICE_TYPENAME: C_0402-33PFC0G550V035-0028-000-035-0028-00033PF; DRAWING: @P3449_B01_LIB.P3449_B01(SCH_1):PAGE12; MAT: C0G; MAX_VOLTAGE: 50V; NV_PN: 035-0028-000; PATH: I58; PHYS_PAGE: 12; ROT: 0; SEC: 1; SIGNAL_MODEL: nv_cap; TOL: 5%; VER: 2; XY: (-4650,5150)
C328 = C: ASSEMBLY: 3V3_DCDC; CDS_LIB: discrete; CDS_PART_NAME: C_0402-1UF,X5R,10%,10V,039-0140-000; CDS_PHYS_PART_NAME: C_0402-1UF,X5R,10%,10V,039-0140-000-039-0140-000,1UF; CDS_SEC: 1; DEVICE_TYPENAME: C_0402-1UFX5R1010V039-0140-000-039-0140-0001UF; DRAWING: @P3449_B01_LIB.P3449_B01(SCH_1):PAGE12; MAT: X5R; MAX_VOLTAGE: 10V; NV_PN: 039-0140-000; PATH: I54; PHYS_PAGE: 12; ROT: 0; SEC: 1; SIGNAL_MODEL: nv_cap; TOL: 10%; VER: 2; XY: (-5450,5800)
C329 = C#1: ASSEMBLY: 3V3_DCDC; CDS_LIB: discrete; CDS_PART_NAME: C_0402-0.1UF,X5R,10%,6.3V,039-0007-000; CDS_PHYS_PART_NAME: C_0402-0.1UF,X5R,10%,6.3V,039-0007-000-0.1UF,039-0007-000; CDS_SEC: 1; CHIPS_PART_NAME: C; DEVICE_TYPENAME: C_0402-01UFX5R1063V039-0007-000-01UF039-0007-000; DRAWING: @P3449_B01_LIB.P3449_B01(SCH_1):PAGE12; MAT: X5R; MAX_VOLTAGE: 6.3V; NV_PN: 039-0007-000; PATH: I69; PHYS_PAGE: 12; ROT: 0; SEC: 1; SIGNAL_MODEL: nv_cap; TOL: 10%; VER: 1; XY: (-8750,5600)
C339 = C#1: ASSEMBLY: 3V3_DCDC; CDS_LIB: discrete; CDS_PART_NAME: C_0402-1UF,X5R,10%,10V,039-0140-000; CDS_PHYS_PART_NAME: C_0402-1UF,X5R,10%,10V,039-0140-000-039-0140-000,1UF; CDS_SEC: 1; CHIPS_PART_NAME: C; DEVICE_TYPENAME: C_0402-1UFX5R1010V039-0140-000-039-0140-0001UF; DRAWING: @P3449_B01_LIB.P3449_B01(SCH_1):PAGE12; MAT: X5R; MAX_VOLTAGE: 10V; NV_PN: 039-0140-000; PATH: I80; PHYS_PAGE: 12; ROT: 0; SEC: 1; SIGNAL_MODEL: nv_capp; SKU: NO STUFF; TOL: 10%; VER: 1; XY: (-5100,6300)
C340 = C#1: ASSEMBLY: 3V3_DCDC; CDS_LIB: discrete; CDS_PART_NAME: C_0805-22UF,X5R,20%,10V,032-1108-000; CDS_PHYS_PART_NAME: C_0805-22UF,X5R,20%,10V,032-1108-000-032-1108-000,22UF; CDS_SEC: 1; CHIPS_PART_NAME: C; DEVICE_TYPENAME: C_0805-22UFX5R2010V032-1108-000-032-1108-00022UF; DRAWING: @P3449_B01_LIB.P3449_B01(SCH_1):PAGE12; MAT: X5R; MAX_VOLTAGE: 10V; NV_PN: 032-1108-000; PATH: I88; PHYS_PAGE: 12; ROT: 0; SEC: 1; SIGNAL_MODEL: nv_cap; TOL: 20%; VER: 1; XY: (-8450,5600)
C341 = C#1: ASSEMBLY: 3V3_DCDC; CDS_LIB: discrete; CDS_PART_NAME: C_0805-22UF,X5R,20%,10V,032-1108-000; CDS_PHYS_PART_NAME: C_0805-22UF,X5R,20%,10V,032-1108-000-032-1108-000,22UF; CDS_SEC: 1; CHIPS_PART_NAME: C; DEVICE_TYPENAME: C_0805-22UFX5R2010V032-1108-000-032-1108-00022UF; DRAWING: @P3449_B01_LIB.P3449_B01(SCH_1):PAGE12; MAT: X5R; MAX_VOLTAGE: 10V; NV_PN: 032-1108-000; PATH: I87; PHYS_PAGE: 12; ROT: 0; SEC: 1; SIGNAL_MODEL: nv_cap; TOL: 20%; VER: 1; XY: (-8150,5600)
L37 = L: ASSEMBLY: 3V3_DCDC; CDS_LIB: discrete; CDS_PART_NAME: L_SMD_4X4-2.2UH,IRON CORE,20%,4.3A,6.1A,0.048OHM,0@0HZ,0HZ,130-0938-000; CDS_PHYS_PART_NAME: L_SMD_4X4-2.2UH,IRON CORE,20%,4.3A,6.1A,0.048OHM,0@0HZ,0HZ,130-0938-000-130-0938-000,2.2UH; CDS_SEC: 1; CONTINUOUS_CURRENT: 4.3A; DC_RESISTANCE: 0.048ohm; DEVICE_TYPENAME: L_SMD_4X4-22UHIRONCORE2043A61A0048OHM00HZ0HZ130-0938-000-130-0938-00022UH; DRAWING: @P3449_B01_LIB.P3449_B01(SCH_1):PAGE12; MAT: IRON CORE; MAX_CURRENT: 6.1A; NV_PN: 130-0938-000; PACK_TYPE: SMD_4X4; PATH: I53; PHYS_PAGE: 12; PLACEMENT_NOTE: CO-LAYOUT WITH L38; Q: 0@0Hz; ROT: 0; SEC: 1; SELF_RESONANCE_FREQ: 0Hz; SIGNAL_MODEL: nv_ind; TOL: 20%; VER: 1; XY: (-4650,5550)
L38 = L: ASSEMBLY: 3V3_DCDC; CDS_LIB: discrete; CDS_PART_NAME: L_SMD_4X4-1.5UH,METAL POWDER,20%,7.4A,8.8A,0.0166OHM,0@0HZ,0HZ,130-0990-000; CDS_PHYS_PART_NAME: L_SMD_4X4-1.5UH,METAL POWDER,20%,7.4A,8.8A,0.0166OHM,0@0HZ,0HZ,130-0990-000-1.5UH,130-0990-000; CDS_SEC: 1; CONTINUOUS_CURRENT: 7.4A; DC_RESISTANCE: 0.0166ohm; DEVICE_TYPENAME: L_SMD_4X4-15UHMETALPOWDER2074A88A00166OHM00HZ0HZ130-0990-000-15UH130-0990-000; DRAWING: @P3449_B01_LIB.P3449_B01(SCH_1):PAGE12; MAT: metal powder; MAX_CURRENT: 8.8A; NV_PN: 130-0990-000; PACK_TYPE: SMD_4X4; PATH: I91; PHYS_PAGE: 12; PLACEMENT_NOTE: CO-LAYOUT WITH L37; Q: 0@0Hz; ROT: 0; SEC: 1; SELF_RESONANCE_FREQ: 0Hz; SIGNAL_MODEL: nv_ind; SKU: NO STUFF; TOL: 20%; VER: 1; XY: (-4650,5400)
R471 = R#1: ASSEMBLY: 3V3_DCDC; CDS_LIB: discrete; CDS_PART_NAME: R_0402-10K,5 %,62.5MW,195-0486-000; CDS_PHYS_PART_NAME: R_0402-10K,5 %,62.5MW,195-0486-000-10K,195-0486-000; CDS_SEC: 1; CHIPS_PART_NAME: R; DEVICE_TYPENAME: R_0402-10K5625MW195-0486-000-10K195-0486-000; DRAWING: @P3449_B01_LIB.P3449_B01(SCH_1):PAGE12; MAX_WATTAGE: 62.5mW; NV_PN: 195-0486-000; PATH: I67; PHYS_PAGE: 12; ROT: 0; SEC: 1; SIGNAL_MODEL: nv_res; TOL: 5%; VER: 1; XY: (-7550,5200)
R472 = R#1: ASSEMBLY: 3V3_DCDC; CDS_LIB: discrete; CDS_PART_NAME: R_0402-0OHM,0.05 OHM,62.5MW,195-2655-000; CDS_PHYS_PART_NAME: R_0402-0OHM,0.05 OHM,62.5MW,195-2655-000-0OHM,195-2655-000; CDS_SEC: 1; CHIPS_PART_NAME: R; DEVICE_TYPENAME: R_0402-0OHM005OHM625MW195-2655-000-0OHM195-2655-000; DRAWING: @P3449_B01_LIB.P3449_B01(SCH_1):PAGE12; MAX_WATTAGE: 62.5mW; NV_PN: 195-2655-000; PATH: I61; PHYS_PAGE: 12; ROT: 0; SEC: 1; SIGNAL_MODEL: nv_res; TOL: 0.05 ohm; VER: 1; XY: (-5900,5800)
R473 = R#1: ASSEMBLY: 3V3_DCDC; CDS_LIB: discrete; CDS_PART_NAME: R_0402-0OHM,0.05 OHM,62.5MW,195-2655-000; CDS_PHYS_PART_NAME: R_0402-0OHM,0.05 OHM,62.5MW,195-2655-000-0OHM,195-2655-000; CDS_SEC: 1; CHIPS_PART_NAME: R; DEVICE_TYPENAME: R_0402-0OHM005OHM625MW195-2655-000-0OHM195-2655-000; DRAWING: @P3449_B01_LIB.P3449_B01(SCH_1):PAGE12; MAX_WATTAGE: 62.5mW; NV_PN: 195-2655-000; PATH: I83; PHYS_PAGE: 12; ROT: 0; SEC: 1; SIGNAL_MODEL: nv_res; TOL: 0.05 ohm; VER: 1; XY: (-5450,4650)
R474 = R: ASSEMBLY: 3V3_DCDC; CDS_LIB: discrete; CDS_PART_NAME: R_0402-8.87K,1 %,62.5MW,195-0459-000; CDS_PHYS_PART_NAME: R_0402-8.87K,1 %,62.5MW,195-0459-000-195-0459-000,8.87K; CDS_SEC: 1; DEVICE_TYPENAME: R_0402-887K1625MW195-0459-000-195-0459-000887K; DRAWING: @P3449_B01_LIB.P3449_B01(SCH_1):PAGE12; MAX_WATTAGE: 62.5mW; NV_PN: 195-0459-000; PATH: I56; PHYS_PAGE: 12; ROT: 0; SEC: 1; SIGNAL_MODEL: nv_res; TOL: 1%; VER: 2; XY: (-4200,4500)
R475 = R: ASSEMBLY: 3V3_DCDC; CDS_LIB: discrete; CDS_PART_NAME: R_0402-0OHM,0.05 OHM,62.5MW,195-2655-000; CDS_PHYS_PART_NAME: R_0402-0OHM,0.05 OHM,62.5MW,195-2655-000-0OHM,195-2655-000; CDS_SEC: 1; DEVICE_TYPENAME: R_0402-0OHM005OHM625MW195-2655-000-0OHM195-2655-000; DRAWING: @P3449_B01_LIB.P3449_B01(SCH_1):PAGE12; MAX_WATTAGE: 62.5mW; NV_PN: 195-2655-000; PATH: I85; PHYS_PAGE: 12; ROT: 0; SEC: 1; SIGNAL_MODEL: nv_res; TOL: 0.05 ohm; VER: 2; XY: (-5000,4900)
R476 = R: ASSEMBLY: 3V3_DCDC; CDS_LIB: discrete; CDS_PART_NAME: R_0402-40.2K,1 %,62.5MW,195-0295-000; CDS_PHYS_PART_NAME: R_0402-40.2K,1 %,62.5MW,195-0295-000-195-0295-000,40.2K; CDS_SEC: 1; DEVICE_TYPENAME: R_0402-402K1625MW195-0295-000-195-0295-000402K; DRAWING: @P3449_B01_LIB.P3449_B01(SCH_1):PAGE12; MAX_WATTAGE: 62.5mW; NV_PN: 195-0295-000; PATH: I86; PHYS_PAGE: 12; ROT: 0; SEC: 1; SIGNAL_MODEL: nv_res; TOL: 1%; VER: 2; XY: (-4200,4850)
R477 = R: ASSEMBLY: 3V3_DCDC; CDS_LIB: discrete; CDS_PART_NAME: R_0402-0OHM,0.05 OHM,62.5MW,195-2655-000; CDS_PHYS_PART_NAME: R_0402-0OHM,0.05 OHM,62.5MW,195-2655-000-0OHM,195-2655-000; CDS_SEC: 1; DEVICE_TYPENAME: R_0402-0OHM005OHM625MW195-2655-000-0OHM195-2655-000; DRAWING: @P3449_B01_LIB.P3449_B01(SCH_1):PAGE12; MAX_WATTAGE: 62.5mW; NV_PN: 195-2655-000; PATH: I71; PHYS_PAGE: 12; ROT: 0; SEC: 1; SIGNAL_MODEL: nv_res; TOL: 0.05 ohm; VER: 2; XY: (-4200,5400)
R478 = R: ASSEMBLY: 3V3_DCDC; CDS_LIB: discrete; CDS_PART_NAME: R_0402-0OHM,0.05 OHM,62.5MW,195-2655-000; CDS_PHYS_PART_NAME: R_0402-0OHM,0.05 OHM,62.5MW,195-2655-000-0OHM,195-2655-000; CDS_SEC: 1; DEVICE_TYPENAME: R_0402-0OHM005OHM625MW195-2655-000-0OHM195-2655-000; DRAWING: @P3449_B01_LIB.P3449_B01(SCH_1):PAGE12; MAX_WATTAGE: 62.5mW; NV_PN: 195-2655-000; PATH: I79; PHYS_PAGE: 12; ROT: 0; SEC: 1; SIGNAL_MODEL: nv_res; SKU: NO STUFF; TOL: 0.05 ohm; VER: 2; XY: (-5100,5850)
R511 = R#1: ASSEMBLY: 3V3_DCDC; CDS_LIB: discrete; CDS_PART_NAME: R_0402-0OHM,0.05 OHM,62.5MW,195-2655-000; CDS_PHYS_PART_NAME: R_0402-0OHM,0.05 OHM,62.5MW,195-2655-000-0OHM,195-2655-000; CDS_SEC: 1; CHIPS_PART_NAME: R; DEVICE_TYPENAME: R_0402-0OHM005OHM625MW195-2655-000-0OHM195-2655-000; DRAWING: @P3449_B01_LIB.P3449_B01(SCH_1):PAGE12; MAX_WATTAGE: 62.5mW; NV_PN: 195-2655-000; PATH: I84; PHYS_PAGE: 12; ROT: 0; SEC: 1; SIGNAL_MODEL: nv_res; SKU: NO STUFF; TOL: 0.05 ohm; VER: 1; XY: (-5300,5150)
U9 = U_BUCK_FET_1PH: ASSEMBLY: 3V3_DCDC; CDS_LIB: power_supply; CDS_PART_NAME: U_BUCK_FET_1PH_QFN_11-MP2384,BUCK,1PH,700KHZ,NONE,0.6V..13V,5%,0.6V,26V,4A,3.6W,316-0613-000; CDS_PHYS_PART_NAME: U_BUCK_FET_1PH_QFN_11-MP2384,BUCK,1PH,700KHZ,NONE,0.6V..13V,5%,0.6V,26V,4A,3.6W,316-0613-000-0.6V,316-0613-000; CDS_SEC: 1; DEVICE_TYPENAME: U_BUCK_FET_1PH_QFN_11-MP2384BUCK1PH700KHZNONE06V13V506V26V4A36W316-0613-000-06V316-0613-000; DRAWING: @P3449_B01_LIB.P3449_B01(SCH_1):PAGE12; MAX_CURRENT: 4A; MAX_VOLTAGE: 26V; MAX_WATTAGE: 3.6W; MODE: Buck; NV_NAME: MP2384; NV_PN: 316-0613-000; OUTPUT_VOLTAGE: 0.6V..13V; PACK_TYPE: QFN_11; PATH: I78; PHASES: 1Ph; PHYS_PAGE: 12; PROGRAMMABLE: None; ROT: 0; SEC: 1; SWITCHING_FREQ: 700KHz; TOL: 5%; VER: 16; XY: (-6500,5550)
U39 = U_VREG_5PIN: ASSEMBLY: 1V8_LDO; CDS_LIB: power_supply; CDS_PART_NAME: U_VREG_5PIN_SOT235-TLV70018,LOW DROP OUT/FIXED,0.25V@0.2A,1.8V..1.8V,2%,[ ],5.5V,0.2A,0.5W,315-0620-000; CDS_PHYS_PART_NAME: U_VREG_5PIN_SOT235-TLV70018,LOW DROP OUT/FIXED,0.25V@0.2A,1.8V..1.8V,2%,[ ],5.5V,0.2A,0.5W,315-0620-000-315-0620-000,[ ]; CDS_SEC: 1; DEVICE_TYPENAME: U_VREG_5PIN_SOT235-TLV70018LOWDROPOUTFIXED025V02A18V18V255V02A05W315-0620-000-315-0620-000; DRAWING: @P3449_B01_LIB.P3449_B01(SCH_1):PAGE12; FORWARD_VOLTAGE: 0.25V@0.2A; MAX_CURRENT: 0.2A; MAX_VOLTAGE: 5.5V; MAX_WATTAGE: 0.5W; NV_NAME: TLV70018; NV_PN: 315-0620-000; OUTPUT_VOLTAGE: 1.8V..1.8V; PACK_TYPE: SOT235; PATH: I42; PHYS_PAGE: 12; ROT: 0; SEC: 1; TOL: 2%; TYPE: Low Drop Out/Fixed; VER: 15; XY: (-6450,1850)

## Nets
3V3_DCDC_BST: R472.1 U9.7(BST)
3V3_DCDC_BST_R: C328.1 R472.2
3V3_IO_PG: R471.2 U9.5(PGOOD) U39.3(EN) ; also on sheet 6 15
3V3_SNUB: C339.2 R478.1
GND: C57.2 C63.2 C67.1 C203.2 C204.2 C207.2 C208.2 C308.2 C313.2 C315.2 C316.2 C318.2 C329.2 C334.2 C338.2 C339.1 C340.2 C341.2 D33.2(A) D34.2(A) D46.2 D63.2 J25.2 J25.3 J48.2 Q46.2(S) R452.2 R453.2 R456.2 R458.2 R460.2 R474.2 R503.2 R504.2 R505.2 R513.2 U9.2(PGND1) U9.3(PGND2) U9.4(PGND3) U9.9(AGND) U39.2(GND1) U39.4(GND2) U58.16(GND) U58.21(PAD) U66.3(GND) U67.16(GND) U67.21(PAD) ; also on sheet 1 3 4 5 6 7 8 9 10 13 14 15 16 19
VDD_1V8: C208.1 U39.5(OUT) ; also on sheet 3 4 6 7 9 19
VDD_3V3_SYS: C63.1 C203.1 C204.1 C207.1 L37.2 L38.2 R471.1 R477.1 U39.1(IN) ; also on sheet 3 4 5 6 7 8 9 18 19
VDD_5V_AO: D32.3(CC) R448.1
VDD_5V_IN: C57.1 C315.1 C318.1 C329.1 C340.1 C341.1 R457.1 R512.1 U9.1(VIN) U58.4(VOUT1) U58.5(VOUT2) U58.6(VOUT3) U58.7(VOUT4) U58.8(VOUT5) U67.4(VOUT1) U67.5(VOUT2) U67.6(VOUT3) U67.7(VOUT4) U67.8(VOUT5) ; also on sheet 3 4 7 10 14 15 19
VDD_5V_USB: C316.1 D32.1(A1) R501.1 R507.1 U66.5(VCC) U67.9(VIN1) U67.10(VIN2) U67.11(VIN3) U67.12(VIN4) U67.13(VIN5) ; also on sheet 16
VDD_DC_JACK: C338.1 D32.2(A2) D34.1(C) D63.1 J25.1 R450.1 R459.1 R515.1 U58.9(VIN1) U58.10(VIN2) U58.11(VIN3) U58.12(VIN4) U58.13(VIN5)
DC_DMODE: R459.2 R460.1 U58.1(DMODE)
DC_EN_UVLO: Q46.3(D) R450.2 R451.1 U58.14(EN_UVLO)
DC_ILIM: R453.1 U58.17(ILIM)
DC_IMON: R456.1 U58.19(IMON)
DC_OVP_SET: R451.2 R452.1 U58.15(OVP)
DC_PGTH: R457.2 R458.1 U58.3(PGTH)
DC_SOFTSTART: C313.1 U58.18(DVDT)
DCJACK_SNUB: C308.1 R515.2
PS_3V3_FB: R473.1 U9.10(FB)
PS_3V3_FB_R: R473.2 R474.1 R475.2 R476.2
PS_3V3_SW: C328.2 L37.1 L38.1 R478.2 R511.1 U9.6(SW)
PS_3V3_SW_FB_SENSE: C327.1 R475.1 R511.2
PS_3V3_SW_FB_SENSE_R: C327.2 R476.1 R477.2
PS_3V3_VCC: C67.2 U9.8(VCC)
SNN_DC_FLT: U58.20(FLT_BAR)
SNN_DC_PGOOD: U58.2(PGOOD)
SNN_UUSB_FLT: U67.20(FLT_BAR)
SNN_UUSB_IMON: U67.19(IMON)
SNN_UUSB_PGOOD: U67.2(PGOOD)
SYS_RST*: U9.11(EN) ; also on sheet 3 19
USB_DC_PPATH_SEL: D33.1(C) D46.1 J48.1 Q46.1(G) R448.2 R482.1
USB_DC_PPATH_SEL2: R482.2 U66.2(A)
UUSB_DMODE: R504.1 R507.2 U67.1(DMODE)
UUSB_EN_UVLO: R501.2 R502.1 U66.4(Y) U67.14(EN_UVLO)
UUSB_ILIM: R505.1 U67.17(ILIM)
UUSB_OVP_SET: R502.2 R503.1 U67.15(OVP)
UUSB_PGTH: R512.2 R513.1 U67.3(PGTH)
UUSB_SOFTSTART: C334.1 U67.18(DVDT)

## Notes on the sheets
sheet 11
- A
- B
- C
- D
- E
- F
- G
- H
- 3V3 & 1V8 POWER SUPPLIES
- 3V3 DCDC
- 1
- 1
- DCR = 48mOhm
- Irms(A) = 4.3A
- Isat(A) = 6.1A
- CO-LAYOUT
- 2
- 2
- 3
- 3
- 1V8 LDO
- 4
- 4
- 5
- 5
- NVIDIA CORPORATION
- 2701 SAN TOMAS
  EXPRESSWAY
- ASSEMBLY
- <ASSEMBLY_DESCRIPTION>
- SANTA CLARA, CA 95050, USA
- PAGE DETAIL
- 3V3 DCDC and 1V8 LDO
- NV_PN
- 600-13449-BASE-400
- ALL NVIDIA DESIGN SPECIFICATIONS, REFERENCE SPECIFICATIONS, REFERENCE BOARDS, FILES, DRAWINGS, DIAGNOSTICS, LISTS AND OTHER DOCUMENTS OR INFORMATION (TOGETHER AND SEPARATELY, 'MATERIALS') ARE BEING PROVIDED 'AS IS'. THE MATERIALS
  MAY
- CONTAIN KNOWN AND UNKNOWN VIOLATIONS OR DEVIATIONS OF INDUSTRY STANDARDS AND SPECIFICATIONS. NVIDIA MAKES NO WARRANTIES, EXPRESSED, IMPLIED, STATUTORY OR OTHERWISE WITH RESPECT TO THE MATERIALS OR OTHERWISE, AND EXPRESSLY DISCLAIMS
  ALL
- PCB REV
- P3449-B01
- PAGE
- 12 OF 23
- IMPLIED WARRANTIES INCLUDING, WITHOUT LIMITATION, THE WARRANTIES OF DESIGN, OF NONINFRINGEMENT, MERCHANTABILITY OR FITNESS FOR A PARTICULAR PURPOSE, OR ARISING FROM A COURSE OF DEALING, TRADE USAGE, TRADE PRACTICE, OR INDUSTRY
  STANDARDS.
- BOM REV
- M
- DATE
- 08-OCT-2022
- A
- B
- C
- D
- E
- F
- G
- H
sheet 12
- A
- B
- C
- D
- E
- F
- G
- H
- DC JACK AND uUSB POWER SOURCE SELECTION
- 1
- 1
- DC JACK
- PLUG 5.5mm 0D, 2.0mm ID
- 2
- 2
- 3
- 3
- 4
- 4
- 5
- 5
- NVIDIA CORPORATION
- 2701 SAN TOMAS
  EXPRESSWAY
- ASSEMBLY
- <ASSEMBLY_DESCRIPTION>
- SANTA CLARA, CA 95050, USA
- PAGE DETAIL
- DC
  Jack
- NV_PN
- 600-13449-BASE-400
- ALL NVIDIA DESIGN SPECIFICATIONS, REFERENCE SPECIFICATIONS, REFERENCE BOARDS, FILES, DRAWINGS, DIAGNOSTICS, LISTS AND OTHER DOCUMENTS OR INFORMATION (TOGETHER AND SEPARATELY, 'MATERIALS') ARE BEING PROVIDED 'AS IS'. THE MATERIALS
  MAY
- CONTAIN KNOWN AND UNKNOWN VIOLATIONS OR DEVIATIONS OF INDUSTRY STANDARDS AND SPECIFICATIONS. NVIDIA MAKES NO WARRANTIES, EXPRESSED, IMPLIED, STATUTORY OR OTHERWISE WITH RESPECT TO THE MATERIALS OR OTHERWISE, AND EXPRESSLY DISCLAIMS
  ALL
- PCB REV
- P3449-B01
- PAGE
- 11 OF 23
- IMPLIED WARRANTIES INCLUDING, WITHOUT LIMITATION, THE WARRANTIES OF DESIGN, OF NONINFRINGEMENT, MERCHANTABILITY OR FITNESS FOR A PARTICULAR PURPOSE, OR ARISING FROM A COURSE OF DEALING, TRADE USAGE, TRADE PRACTICE, OR INDUSTRY
  STANDARDS.
- BOM REV
- M
- DATE
- 08-OCT-2022
- A
- B
- C
- D
- E
- F
- G
- H
